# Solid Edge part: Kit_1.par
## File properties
Sűrűség: 0,000 kg/m^3
Pontosság: 0,990
Author: ahadarics
Last saved by: ahadarics
Revision: 76
Username: ahadarics
Dokumentum tartalom típus: 0
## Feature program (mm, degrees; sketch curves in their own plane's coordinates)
base feature "unnamed BaseFeature 1"
thread "unnamed Thread 1"
chamfer "unnamed Chamfer 1"
sketch for "Furat_1" plane through (0, -45, 8.5) normal (0, 0, 1) x-axis (0, 1, 0)
  hole centre (0, 0) bore radius 2.067
hole "Furat_1" nominal diameter 5 finite  ThreadDepth = 4.5 mm
chamfer "Letörés_2" setback 0.5
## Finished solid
Body 1: solid body, 48 faces, 52 edges, 6 vertices.
  Faces by surface: plane 16, cylinder 14, cone 11, torus 7
  Edges by curve: circle 45, line 6, intersection 1
Bounding box of the edges (mm; curved faces can reach further): 19.000 x 28.500 x 18.100, from (-9.5, -67.5, -9.5) to (9.5, -39, 8.6).
Cylindrical faces by radius (mm): R2.06 x1, R2.067 x1, R3.25 x2, R3.55 x1, R4.5 x1, R4.55 x1, R5.55 x1, R5.6 x1, R6.85 x1, R8 x2, R8.6 x1, R9.5 x1
Conical faces (half-angle, radius in mm at the cone's reference point): 8.8315 deg R4.75 x1, 15 deg R5.55 x1, 20.542 deg R3.55 x1, 24.3997 deg R3.55 x1, 27.3182 deg R3.0335 x1, 29.1112 deg R4.1553 x1, 45 deg R2.567 x1, 45 deg R4.65 x1, 45 deg R4.8 x1, 45 deg R8 x1, 60 deg R7.425 x1
Toroidal faces (ring radius, tube radius in mm): R3.2 r0.2 x1, R3.3 r0.3 x1, R4.3301 r0.2 x1, R4.35 r0.2 x1, R5.35 r0.2 x1, R5.4 r0.2 x2
Planar faces by outward normal: +y 5, +z 2, -y 9
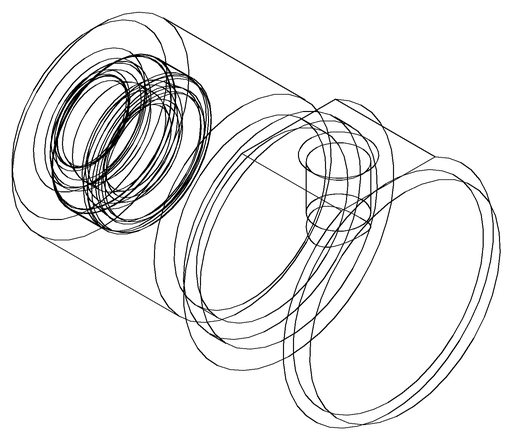
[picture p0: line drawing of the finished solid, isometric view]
